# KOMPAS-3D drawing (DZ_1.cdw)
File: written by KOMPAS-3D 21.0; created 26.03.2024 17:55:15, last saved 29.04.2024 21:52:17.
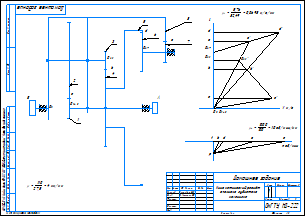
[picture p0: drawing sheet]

Sheet 1: A3, landscape

Document properties: Автор: TrapoCarrier

Title block, sheet 1: Наименование: Кинематический расчёт / сложного зубчатого / механизма; designation: Домашнее задание; Количество листов документа: 1; organisation: ОмГТУ; НД-222; Форматы листов документа: A3; Литера: У; stored path: D:\ДЗ\ТММ\ДЗ1\ДЗ_1.cdw; Разработал: Лехнович М.К.; Проверил: Гавриленко С.В.

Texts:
  ␣V =  5,76 82,49  = 0,0698 м/с/мм
  Symbol type A
  ␣n =  1000 100  = 10 об/мин/мм
  n об/мин
Dimensions and other numbers on the sheet: 8; 7; 6; 5; 4; 3; 2; 1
